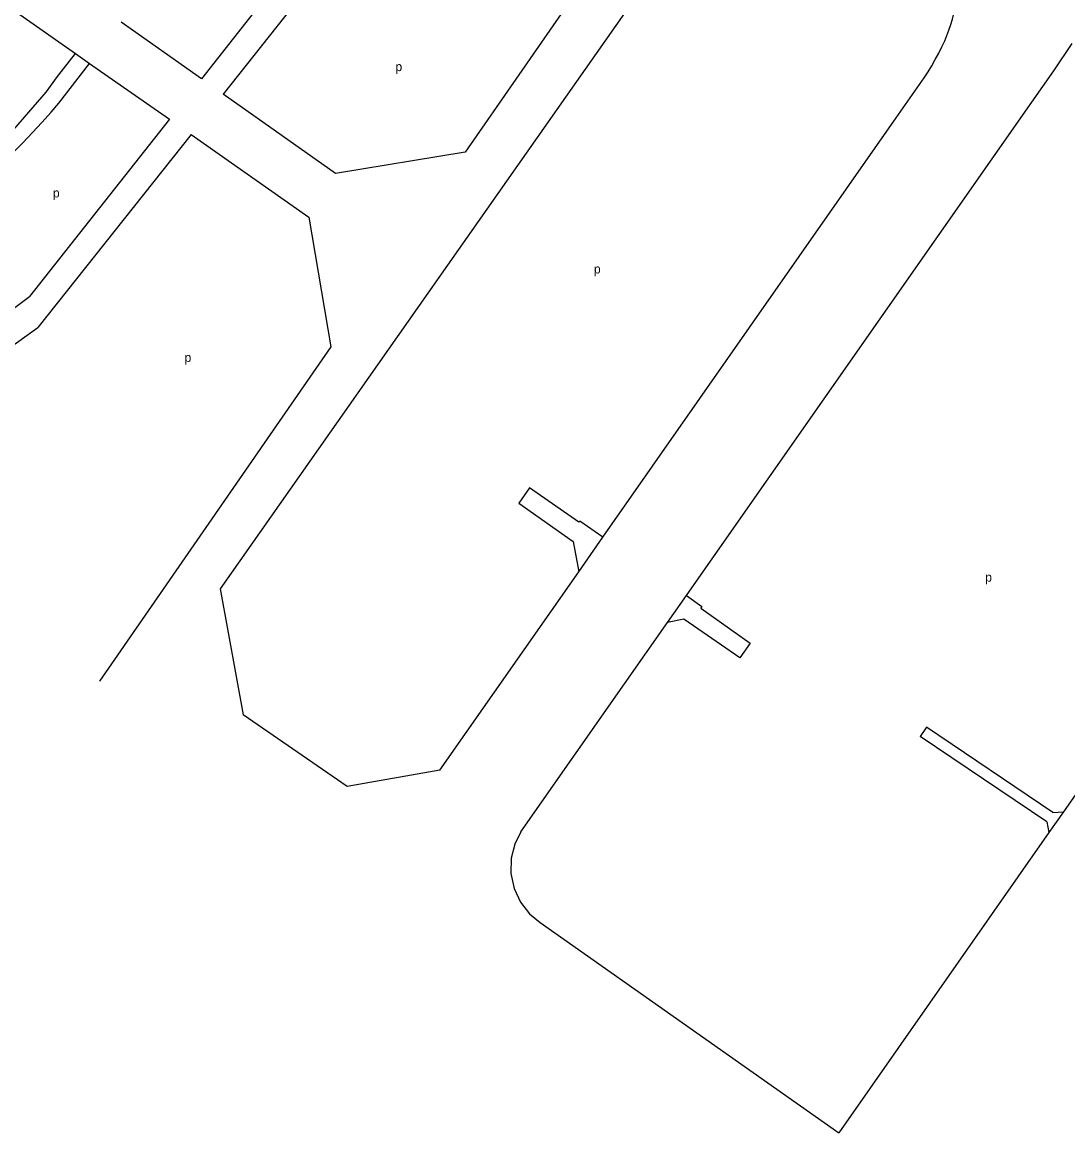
# Model space of a CAD drawing. Extents: x 153608 to 155459, y 385052 to 386919.
# Drawn here: x 154362.6 to 154824.5, y 385051.8 to 385542.2 of the extents above; entities that cross this region are included whole.
import ezdxf

# ---------------------------------------------------------------- set-up
doc = ezdxf.new("R2010")
doc.units = 0
doc.layers.add('BLT_Basislijn', color=7, linetype='Continuous')
doc.layers.add('BLT_Centroide', color=7, linetype='Continuous')

msp = doc.modelspace()

# ---------------------------------------------------------------- linework, layer by layer
at = {"layer": 'BLT_Basislijn'}
for p, q in [((154669.97, 385645.98), (154558.38, 385484.76)), ((154537.42, 385638.43), (154441.78, 385517.22)), ((154685.3, 385626.86), (154450.13, 385291.98)), ((154541.49, 385623.9), (154451.39, 385510.44)), ((154441.78, 385517.22), (154406.39, 385542.21)), ((154386.19, 385528.38), (154392.39, 385524.04)), ((154378.79, 385506.39), (154392.39, 385524.04)), ((154392.39, 385524.04), (154427.66, 385499.32)), ((154427.66, 385499.32), (154365.91, 385421.07)), ((154437.24, 385492.61), (154369.6, 385407.43)), ((154350.15, 385409.32), (154365.91, 385421.07)), ((154338.87, 385385.47), (154369.6, 385407.43)), ((154498.92, 385398.86), (154396.76, 385251.27)), ((154608.49, 385299.51), (154619.21, 385314.78)), ((154547.18, 385211.96), (154608.49, 385299.51)), ((154450.13, 385291.98), (154460.19, 385236.4)), ((154647.76, 385277.17), (154656.05, 385289)), ((154506.19, 385204.72), (154460.19, 385236.4)), ((154762.17, 385230.85), (154759.38, 385226.7)), ((154818, 385193.26), (154762.17, 385230.85)), ((154815.21, 385189.11), (154759.38, 385226.7)), ((154815.21, 385189.11), (154816.21, 385184.34)), ((154822.59, 385193.44), (154816.21, 385184.34)), ((154818, 385193.26), (154822.59, 385193.44))]:
    msp.add_line(p, q, dxfattribs=at)
for points in [[(154399.99, 385546.73), (154379.63, 385561.1), (154374.24, 385591.68), (154371.37, 385593.71), (154380.3, 385606.38), (154392.94, 385597.52), (154450.59, 385680.49), (154401.66, 385714.83), (154343.04, 385632.56), (154355.71, 385623.64), (154346.8, 385610.92), (154282.5, 385655.99), (154251.78, 385650.69), (154235.63, 385661.35), (154222.76, 385642.9), (154386.19, 385528.38)], [(154770.17, 385533.93), (154771.13, 385536.3), (154772.02, 385538.7), (154772.83, 385541.13), (154773.57, 385543.58), (154774.22, 385546.06), (154774.8, 385548.55), (154775.3, 385551.06), (154775.73, 385553.58), (154776.07, 385556.12), (154776.15, 385556.86)], [(154656.05, 385289), (154803.81, 385500), (154818.36, 385520.75), (154826.5, 385532.87)], [(154761.08, 385517.58), (154762.79, 385520.26), (154764.44, 385522.98), (154766.01, 385525.74), (154767.52, 385528.54), (154768.96, 385531.38), (154770.17, 385533.93)], [(154373.23, 385511.3), (154378.2, 385518.23), (154386.19, 385528.38)], [(154619.21, 385314.78), (154748.78, 385500), (154761.08, 385517.58)], [(154241.19, 385434.32), (154247.13, 385425.12), (154252.16, 385421.84), (154256.88, 385420.43), (154263.03, 385420.45), (154267.75, 385421.87), (154270.96, 385423.71), (154289.95, 385435.34), (154302.79, 385444.03), (154319.26, 385456.53), (154334.92, 385470.02), (154353.27, 385488.21), (154373.23, 385511.3)], [(154558.38, 385484.76), (154501.08, 385475.36), (154451.39, 385510.44)], [(154327.29, 385455.36), (154331.94, 385459.36), (154336.54, 385463.42), (154341.08, 385467.54), (154345.58, 385471.72), (154350.01, 385475.95), (154354.39, 385480.25), (154358.71, 385484.6), (154362.98, 385489), (154367.19, 385493.47), (154371.34, 385497.98), (154375.43, 385502.55), (154378.79, 385506.39)], [(154437.24, 385492.61), (154489.23, 385456.18), (154498.92, 385398.86)], [(154996.36, 385443.35), (154914.01, 385325.65), (154903.03, 385310.14), (154900, 385306.26), (154851.76, 385235.11), (154822.59, 385193.44)], [(154619.21, 385314.78), (154608.98, 385321.89), (154608.47, 385321.35), (154586.72, 385336.54), (154582.05, 385329.86), (154606.03, 385312.84), (154608.49, 385299.51)], [(154656.05, 385289), (154662.91, 385284.12), (154662.4, 385283.41), (154684.17, 385268.02), (154679.68, 385261.47), (154654.93, 385278.51), (154647.76, 385277.17)], [(154582.96, 385184.69), (154628.71, 385250), (154647.76, 385277.17)], [(154547.18, 385211.96), (154506.19, 385204.72)], [(154582.96, 385184.69), (154580.26, 385179.25), (154578.68, 385173), (154578.53, 385166.29), (154579.95, 385159.63), (154582.82, 385153.56), (154586.8, 385148.49), (154591.48, 385144.63)], [(154816.21, 385184.34), (154723.41, 385051.76)], [(154591.48, 385144.63), (154723.41, 385051.76)]]:
    msp.add_lwpolyline(points, dxfattribs=at)

# ---------------------------------------------------------------- texts
at = {"layer": 'BLT_Centroide'}
for p in [(154527.53, 385520.6), (154376.21, 385464.83), (154615.21, 385431.25), (154434.36, 385392.17), (154788.06, 385295.14)]:
    msp.add_text('p', height=4, dxfattribs=at).set_placement(p)

doc.saveas('drawing.dxf')
